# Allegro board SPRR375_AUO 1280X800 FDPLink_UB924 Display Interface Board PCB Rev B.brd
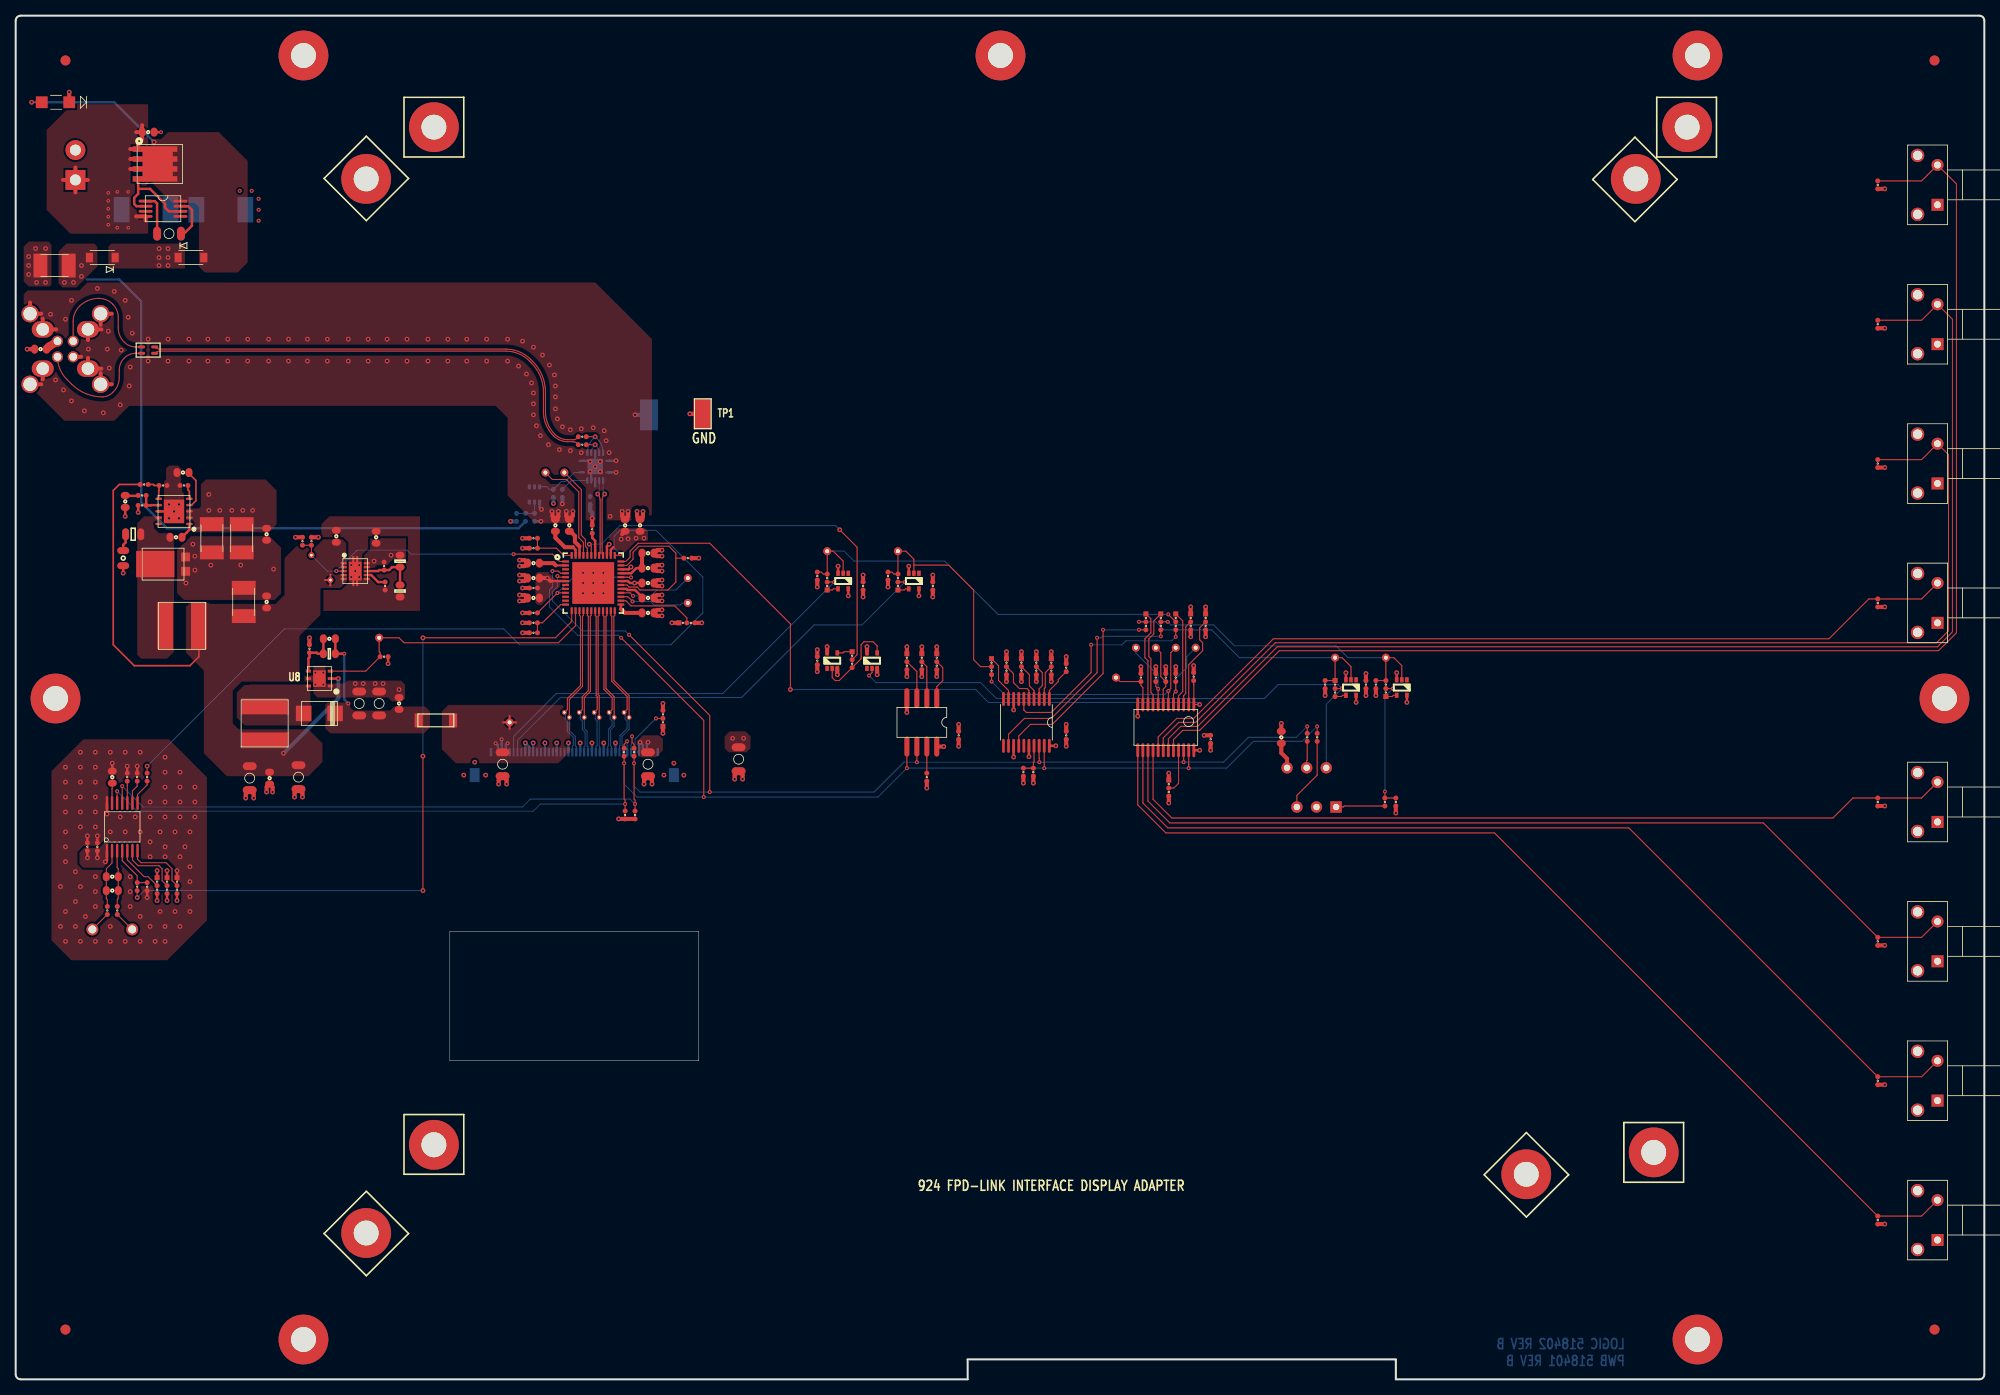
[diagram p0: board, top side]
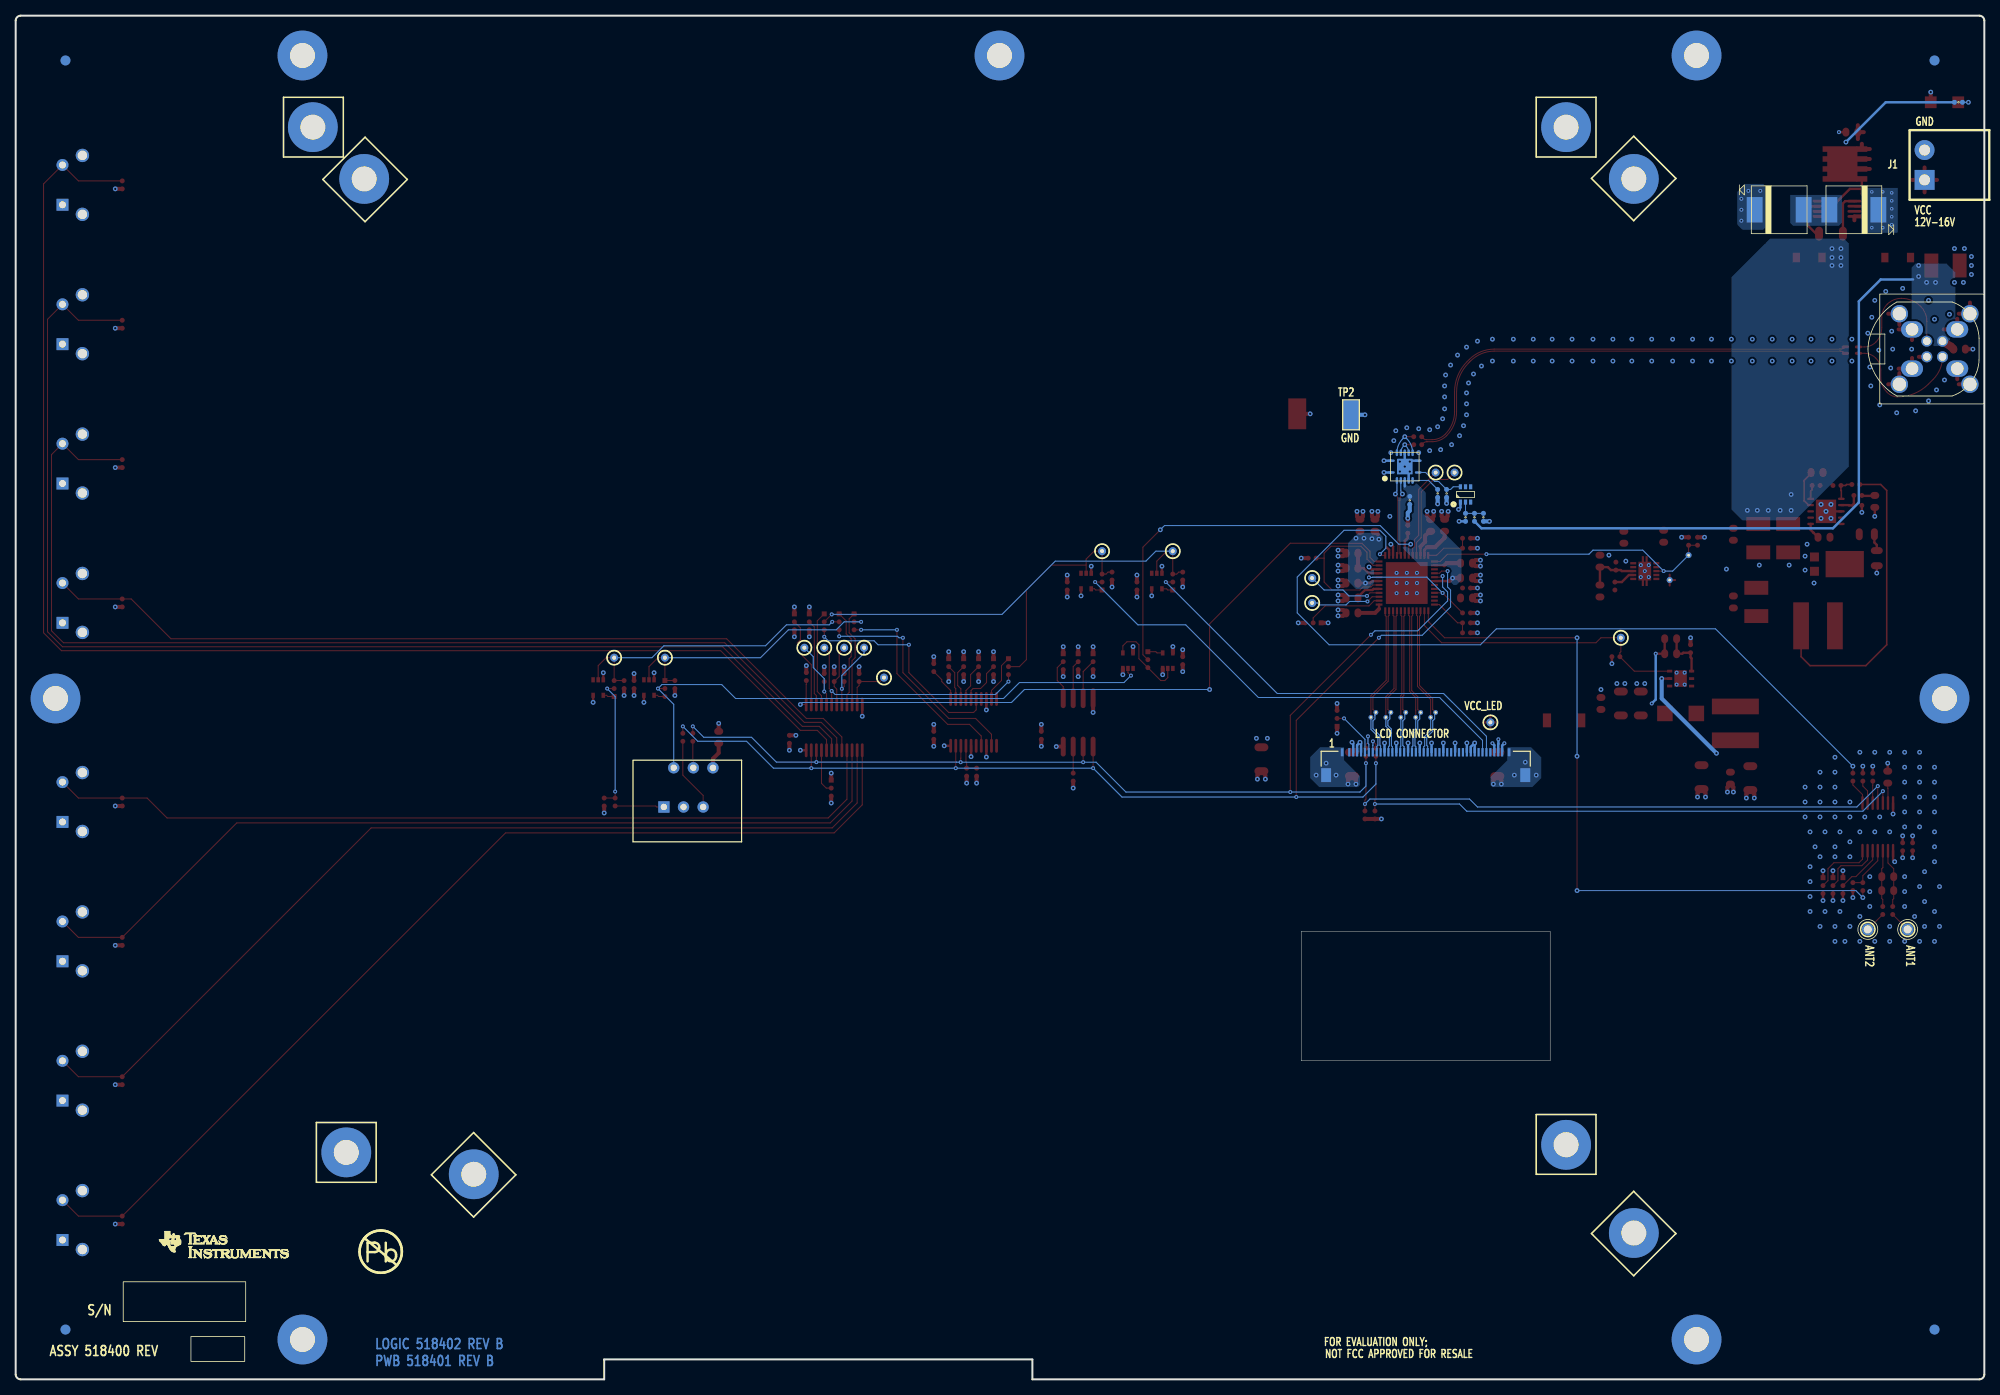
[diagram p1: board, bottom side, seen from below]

Outline 251.08 x 173.99 mm; copper layers: TOP, L2_GND, L3_PWR, BOTTOM. Coordinates in mm from the lower left corner of the outline.
Outline path: circle c53.34,29.97 r1.52 ; circle c208.91,28.96 r1.52 ; 0,173.35 arc(0.19,173.8) 0.64,173.99 250.44,173.99 arc(250.89,173.8) 251.08,173.35 251.08,0.64 arc(250.89,0.19) 250.44,0 176.02,0 176.02,2.54 121.41,2.54 121.41,0 0.64,0 arc(0.19,0.19) 0,0.64 0,173.35 ; 55.37,57.15 55.37,40.64 87.12,40.64 87.12,57.15 55.37,57.15

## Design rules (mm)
net group DP1: nets N48074547 N48074849
net group RIN+: nets N48057923 RIN+
net group RIN-: nets N48057914 RIN-
net group RXN: nets RXINOCLK+ RXINOCLK- RXNO0+ RXNO0- RXNO1+ RXNO1- RXNO2+ RXNO2- RXNO3+ RXNO3-

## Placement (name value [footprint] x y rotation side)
C1  2.7nF  [C603-35X45]  21.34 115.7 0 top
C2  39nF  [C603-35X45]  13.97 112.01 270 top
C3  30pF  [C402-25]  16.13 111.51 0 top
C4  4.7uF  [C603-35X45]  68.83 108.97 90 top
C5  4.7uF  [C603-35X45]  70.61 108.97 270 top
C6  4.7uF  [C603-35X45]  77.72 108.97 270 top
C7  0.1uF  [C402-25]  73.53 108.46 270 top
C8  0.1uF  [C402-25]  72.26 119.25 0 top
C9  0.1uF  [C402-25]  72.26 120.27 0 top
C10  0.22uF  [C603-35X45]  32 107.82 270 top
C11  2.2uF  [C603-35X45]  40.89 107.57 90 top
C12  0.1uF  [C603-35X45]  20.45 107.44 180 top
C13  10uF  [C603-35X45]  45.97 107.44 90 top
C14  4.7uF  [C1210-70X102]  25.02 107.31 270 top
C15  4.7uF  [C1210-70X102]  28.83 107.31 270 top
C16  4.7uF  [C603-35X45]  80.64 105.41 180 top
C17  NP  [C805-35X60]  13.72 104.78 270 top
C18  4.7uF  [C603-35X45]  66.04 104.14 180 top
C19  5.6pF  [C402-25]  46.99 103.76 270 top
C20  4.7uF  [C603-35X45]  80.64 103.5 180 top
C21  4.7uF  [C603-35X45]  66.04 102.23 180 top
C22  4.7uF  [C603-35X45]  80.64 101.6 180 top
C23  0.001uF  [C402-25]  47.12 101.22 270 top
C24  0.1uF  [C402-25]  108.08 101.22 90 top
C25  0.1uF  [C402-25]  116.97 101.22 90 top
C26  0.01uF  [C402-25]  66.04 100.97 0 top
C27  4.7uF  [C603-35X45]  80.64 99.69 0 top
C28  47uF  [C1210-70X102]  29.08 99.19 90 top
C29  0.22uF  [C603-35X45]  32 99.19 90 top
C30  4.7uF  [C603-35X45]  80.64 97.79 0 top
C31  330pF  [C603-35X45]  40.01 94.49 180 top
C32  0.01uF  [C402-25]  102.23 91.69 90 top
C33  0.1uF  [C402-25]  172.21 88.65 90 top
C34  10uF  [C1206-40X70]  43.81 86.23 90 top
C35  NO-POP  [C1206-40X70]  46.35 86.23 90 top
C36  0.1uF  [C603-35X45]  48.9 86.23 270 top
C37  0.1uF  [C402-25]  120.27 82.17 270 top
C38  0.1uF  [C402-25]  133.99 82.17 90 top
C39  10uF  [C603-35X45]  161.42 81.92 90 top
C40  0.1uF  [C402-25]  152.4 81.66 90 top
C41  10uF  [C1206-40X70]  92.2 79.12 90 top
C42  10uF  [C1206-40X70]  62.1 78.49 90 top
C43  10uF  [C1206-40X70]  80.64 78.49 270 top
C44  0.1uF  [C402-25]  129.79 77.47 270 top
C45  1uF  [C603-35X45]  12.32 76.83 90 top
C46  10uF  [C1206-40X70]  36.07 76.83 90 top
C47  10uF  [C1206-40X70]  29.84 76.71 270 top
C48  0.1uF  [C603-35X45]  32.38 76.71 90 top
C49  0.01uF  [C402-25]  9.14 67.94 90 top
C50  1uF  [C402-25]  10.41 67.94 90 top
C51  NP  [C603-35X45]  12.32 64.14 0 top
C52  0.01uF  [C402-25]  16.76 62.87 90 top
C53  NP  [C603-35X45]  12.32 62.36 0 top
C54  0.1uF  [C603-35X45]  3.17 131.44 180 top
C55  4.7uF  [C1210-70X102]  4.95 142.11 0 top
C56  1uF  [C402-25]  36.58 106.93 270 top
C57  2.2uF  [C1206-40X70]  19.56 146.18 0 top
C58  0.22uF  [C603-35X45]  16.89 159.13 0 top
C59  0.01uF  [C402-25]  63.88 109.98 90 bottom
C60  0.01uF  [C402-25]  73.28 112.14 270 bottom
D1  MBRX140-TP  [SOD123-36X48]  11.05 143.13 180 top
D2  PDS760  [DIODE-POWERDI5]  18.8 104.01 180 top
D3  MBRA340T3  [SMA2-78SQ]  38.73 84.96 180 top
D4  SMCJ30A-13-F  [SMC-80X128]  16.64 149.22 0 bottom
D5  MBRX140-TP  [SOD123-36X48]  22.35 143.13 0 top
D6  SMCJ14A-13-F  [SMC-80X128]  26.16 149.22 180 bottom
DS1  LED_GRN  [LED1206-59X59]  5.08 162.94 180 top
FL1  DLW21SN900HQ2  [EMI-36X15-DLW21-RDPADS]  16.89 131.32 0 top
J1  Phoenix - 1803277  [CON2R-150]  7.62 153.03 90 bottom
J2  HEADER 40  [CON40-HD1S040H]  71.25 80.01 180 bottom
J3  MOLEX 39-53-2064  [FPC6_1P25_TH_RA]  168.4 73.03 180 bottom
L1  BLM18AG221SN1D  [L603-35X45]  79.63 108.97 270 top
L2  BLM18AG221SN1D  [L603-35X45]  66.04 99.69 180 top
L3  22uH  [IND2-79X236-6MM]  21.21 96.14 0 top
L4  BLM41PG750SN1L  [FB1806-41X70]  53.59 84.07 0 top
L5  4.7uH  [IND2-79X236-6MM]  31.75 83.69 90 top
MH1  NP  [MHP125-250]  36.7 168.91 0 top
MH2  NP  [MHP125-250]  125.6 168.91 0 top
MH3  NP  [MHP125-250]  44.7 153.16 0 top
MH4  NP  [MHP125-250]  206.63 153.16 0 top
MH5  NP  [MHP125-250]  5.08 86.87 0 top
MH6  NP  [MHP125-250]  246 86.87 0 top
MH7  NP  [MHP125-250]  192.66 26.16 0 top
MH8  NP  [MHP125-250]  44.7 18.67 0 top
MH9  NP  [MHP125-250]  36.7 5.08 0 top
MH10  NP  [MHP125-250]  214.5 5.08 0 top
NOREF  -  []  158.68 68.78 90 top
NOREF#2  -  []  245.87 0 90 top
NOREF#3  -  [unnamed#2]  6.35 6.35 0 top
NOREF#4  -  []  168.4 73.03 0 top
NOREF#5  -  [unnamed#2]  244.73 168.28 0 top
NOREF#6  -  []  -252.73 -240.28 0 top
NOREF#7  -  []  158.68 68.78 0 top
NOREF#8  -  [unnamed#2]  6.35 168.28 0 top
NOREF#9  -  []  55.37 40.64 90 top
NOREF#10  -  []  167.15 78.02 0 top
NOREF#11  -  []  55.37 40.64 0 top
NOREF#12  -  []  253.49 0 90 top
NOREF#13  -  []  -252.73 -240.28 0 top
NOREF#14  -  [unnamed#2]  214.5 168.91 0 top
NOREF#15  -  [unnamed#2]  244.73 6.35 0 top
NOREF#16  -  []  0 173.35 0 top
NOREF#17  -  [unnamed#2]  6.35 168.28 180 bottom
NOREF#18  -  [unnamed#2]  208.91 28.96 180 bottom
NOREF#19  -  []  233.68 15.24 180 bottom
NOREF#20  -  [unnamed#2]  6.35 6.35 180 bottom
NOREF#21  -  [unnamed#2]  53.34 159.77 180 bottom
NOREF#22  -  [unnamed#2]  53.34 29.92 180 bottom
NOREF#23  -  [unnamed#2]  244.73 6.35 180 bottom
NOREF#24  -  [unnamed#2]  213.18 159.77 180 bottom
NOREF#25  -  [unnamed#2]  244.73 168.28 180 bottom
NOREF#26  -  []  207.9 12.83 180 bottom
P2  D4S10E-40MA5-C/D4S20G-400A5-C  [CON_MB261-D4S10E_COMBO]  5.33 132.46 270 bottom
Q1  BSS138PS  [SOT363-16X45]  66.17 112.9 180 bottom
Q3  SQJ422EP  [PWR-Q5A-SLPS319]  15.62 155.07 270 top
R1  60.4K  [R402-25]  16.38 114.17 0 top
R2  11.5K  [R402-25]  18.8 114.05 0 top
R3  133K  [R402-25]  21.46 114.05 180 top
R4  5.9K  [R402-25]  16.13 112.78 180 top
R5  NP  [R805-35X60]  14.99 107.82 180 top
R6  40.2K  [R402-25]  66.04 107.31 180 top
R7  133K  [R402-25]  37.72 106.93 90 top
R8  NP  [R402-25]  66.04 106.05 0 top
R9  10K  [R402-25]  85.72 104.78 180 top
R10  15.8K  [R603-35X45]  49.02 104.39 270 top
R11  10K  [R402-25]  102.23 102.49 90 top
R12  10K  [R402-25]  111.25 102.49 90 top
R13  4.99K  [R603-35X45]  49.02 100.58 270 top
R14  2K  [R402-25]  66.04 97.79 0 top
R15  40.2K  [R402-25]  66.04 96.52 180 top
R16  NP  [R402-25]  66.04 95.25 0 top
R17  10K  [R402-25]  37.47 93.22 270 top
R18  69.8K  [R603-35X45]  40.01 92.58 0 top
R19  10K  [R402-25]  46.99 92.2 0 top
R20  2K  [R402-25]  133.99 90.81 90 top
R21  10K  [R402-25]  150.24 89.66 270 top
R22  10K  [R402-25]  143.51 89.53 270 top
R23  10K  [R402-25]  145.41 89.53 270 top
R24  10K  [R402-25]  146.69 89.53 270 top
R25  10K  [R402-25]  147.96 89.53 270 top
R26  10K  [R402-25]  167 88.65 90 top
R27  10K  [R402-25]  173.48 88.65 90 top
R28  0  [R402-25]  164.72 81.92 270 top
R29  0  [R402-25]  165.99 81.92 270 top
R30  NP  [R402-25]  77.6 80.01 90 top
R31  NP  [R402-25]  78.87 80.01 270 top
R32  10K  [R402-25]  128.52 77.47 90 top
R33  0  [R402-25]  14.22 76.83 270 top
R34  0  [R402-25]  15.49 76.83 270 top
R35  0  [R402-25]  16.76 76.83 270 top
R36  2K  [R402-25]  116.2 76.83 270 top
R37  100  [R402-25]  174.62 73.66 270 top
R38  NP  [R402-25]  176.02 73.66 270 top
R39  5.9K  [R402-25]  77.72 72.01 90 top
R40  5.9K  [R402-25]  78.99 72.01 90 top
R41  0  [R402-25]  15.49 62.87 270 top
R42  0  [R402-25]  11.68 59.82 90 top
R43  0  [R402-25]  12.95 59.82 90 top
R44  1K  [R402-25]  3.3 162.94 0 bottom
R45  10K  [R402-25]  69.72 113.03 90 bottom
R46  10K  [R402-25]  68.58 113.03 270 bottom
R47  11.5K  [R402-25]  65.02 109.98 90 bottom
R48  2K  [R402-25]  66.17 109.98 90 bottom
R49  10K  [R402-25]  237.49 152.4 90 top
R50  10K  [R402-25]  237.49 134.62 90 top
R51  10K  [R402-25]  237.49 116.84 90 top
R52  10K  [R402-25]  237.49 99.06 90 top
R53  10K  [R402-25]  237.49 73.66 90 top
R54  10K  [R402-25]  237.49 38.1 90 top
R55  10K  [R402-25]  237.49 55.88 90 top
R56  10K  [R402-25]  237.49 20.32 90 top
RJ1  100.A  [JMP402-25]  103.5 101.22 90 top
RJ2  100.A  [JMP402-25]  112.52 101.22 90 top
RJ3  0  [JMP402-25]  144.15 97.16 270 top
RJ4  0  [JMP402-25]  146.05 97.16 270 top
RJ5  0  [JMP402-25]  147.96 97.16 270 top
RJ6  10K.A  [JMP402-25]  149.86 97.16 270 top
RJ7  10K.A  [JMP402-25]  151.76 97.16 270 top
RJ8  0  [JMP402-25]  85.09 96.52 0 top
RJ9  100.A  [JMP402-25]  106.68 92.33 270 top
RJ10  10K.A  [JMP402-25]  113.67 92.08 270 top
RJ11  10K.A  [JMP402-25]  115.57 92.08 270 top
RJ12  10K.A  [JMP402-25]  117.47 92.08 270 top
RJ13  0  [JMP402-25]  124.46 91.44 270 top
RJ14  0  [JMP402-25]  126.36 91.44 270 top
RJ15  0  [JMP402-25]  128.27 91.44 270 top
RJ16  0  [JMP402-25]  130.18 91.44 270 top
RJ17  0  [JMP402-25]  132.08 91.44 270 top
RJ18  100.A  [JMP402-25]  168.28 88.65 270 top
RJ19  100.A  [JMP402-25]  174.75 87.63 90 top
RJ20  NP  [JMP402-25]  82.55 83.82 90 top
RJ21  10K.A  [JMP402-25]  147.07 75.95 270 top
RJ22  0  [JMP402-25]  18.03 63.5 270 top
RJ23  0  [JMP402-25]  19.3 63.5 270 top
RJ24  0  [JMP402-25]  20.57 63.5 270 top
SW1  np-ksl0v411lft  [SW2-PUSH-KSL0V]  245.11 152.4 90 top
SW2  np-ksl0v411lft  [SW2-PUSH-KSL0V]  245.11 134.62 90 top
SW3  np-ksl0v411lft  [SW2-PUSH-KSL0V]  245.11 116.84 90 top
SW4  np-ksl0v411lft  [SW2-PUSH-KSL0V]  245.11 99.06 90 top
SW5  np-ksl0v411lft  [SW2-PUSH-KSL0V]  245.11 73.66 90 top
SW6  np-ksl0v411lft  [SW2-PUSH-KSL0V]  245.11 38.1 90 top
SW7  np-ksl0v411lft  [SW2-PUSH-KSL0V]  245.11 55.88 90 top
SW8  np-ksl0v411lft  [SW2-PUSH-KSL0V]  245.11 20.32 90 top
TP1  TPSLP  [TP1-70X135]  87.63 123.19 0 top
TP2  TPSLP  [TP1-70X135]  80.77 123.06 180 bottom
TP3  NP  [TP1-4020]  69.98 115.7 180 bottom
TP4  NP  [TP1-4020]  67.56 115.7 180 bottom
TP5  NP  [TP1-4020]  112.52 105.66 180 bottom
TP6  NP  [TP1-4020]  103.5 105.66 180 bottom
TP7  RD30  [TP-30RD13]  37.72 105.16 0 bottom
TP8  NP  [TP1-4020]  85.72 102.23 180 bottom
TP9  RD30  [TP-30RD13]  40.13 101.98 0 bottom
TP10  NP  [TP1-4020]  85.72 99.06 180 bottom
TP11  NP  [TP1-4020]  46.35 94.61 270 bottom
TP12  NP  [TP1-4020]  150.5 93.34 0 bottom
TP13  NP  [TP1-4020]  147.96 93.34 0 bottom
TP14  NP  [TP1-4020]  145.41 93.34 0 bottom
TP15  NP  [TP1-4020]  142.88 93.34 0 bottom
TP16  NP  [TP1-4020]  174.75 92.08 180 bottom
TP17  NP  [TP1-4020]  168.28 92.08 180 bottom
TP18  NP  [TP1-4020]  140.34 89.53 0 bottom
TP19  NP  [TP-24RD12]  77.6 85.09 90 bottom
TP20  NP  [TP-24RD12]  75.69 85.09 90 bottom
TP21  NP  [TP-24RD12]  73.79 85.09 90 bottom
TP22  NP  [TP-24RD12]  71.88 85.09 90 bottom
TP23  NP  [TP-24RD12]  69.98 85.09 90 bottom
TP24  NP  [TP-24RD12]  78.23 84.45 90 bottom
TP25  NP  [TP-24RD12]  76.33 84.45 90 bottom
TP26  NP  [TP-24RD12]  74.42 84.45 90 bottom
TP27  NP  [TP-24RD12]  72.52 84.45 90 bottom
TP28  NP  [TP-24RD12]  70.61 84.45 90 bottom
TP29  NP  [TP1-4020]  62.99 83.82 180 bottom
TP30  TestPoint1  [TP1-6040]  14.86 57.4 180 bottom
TP31  TestPoint1  [TP1-6040]  9.78 57.4 180 bottom
U1  TPS54361QDPRTQ1  [DPR10]  20.19 110.74 90 top
U2  TPS74701  [DRC10-11X33]  43.31 103.12 270 top
U3  SN74LVC1G04DCK  [DCK-5]  105.54 101.85 180 top
U4  SN74LVC1G04DCK  [DCK-5]  114.55 101.85 180 top
U5  DS90UB924-Q1  [RHS48-11X34]  73.66 101.6 270 top
U6  SN74LVC1G04DCK  [DCK-5]  104.14 91.69 0 top
U7  SN74LVC1G04DCK  [DCK-5]  109.22 91.69 0 top
U8  LM2735XSD/NOPB  [NGG6]  38.73 89.41 90 top
U9  NP-SN74LVC1G04DCK  [DCK-5]  170.31 88.27 180 top
U10  SN74LVC1G04DCK  [DCK-5]  176.78 88.27 180 top
U11  24WC256  [SO8-25X75-295]  115.57 83.82 180 top
U12  TLC59108IPW  [PW20-14X70]  128.91 83.82 180 top
U13  PCF8575  [PW24-14X70]  146.69 83.19 180 top
U14  RF430CL330H  [PW14-12X70]  13.59 70.48 0 top
U16  LM74610  [DGK8-14X70]  18.8 149.35 270 top
U17  HD3SS3411-Q1  [RWA14]  73.91 116.46 180 bottom

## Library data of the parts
C1 C2 C12 C17 C57 = CAP NP_0: Tolerance: X; User Part Number: X
C3 C50 C56 = CAP NP_0: Tolerance: TOLERANCE; User Part Number: USERPART#
C4-C6 C10 C16 C18 C20-C22 C27 C29 C30 C39 C43 C58 = CAP: Tolerance: X; User Part Number: X
C7 C24-C26 C32 C33 C38 C40 C44 C49 C52 C59 C60 = CAP: Tolerance: TOLERANCE; User Part Number: USERPART#
C8 C9 = CAP: Tolerance: TOLERANCE; User Part Number: USERPART#; signal model: CAP_C402-25_0.1UF
C11 C13 C31 C34-C36 C47 C48 C54 = CAP NP: Tolerance: X; User Part Number: X
C14 C15 C55 = CAP_AM_0805_10uf_x7r_10v_10_X: User Part Number: X; Tolerance: X
C19 = Cap 100nF Cermc 16V 10% 603_0: Tolerance: TOLERANCE; User Part Number: USERPART#
C23 = CAP NP: Tolerance: TOLERANCE; User Part Number: USERPART#
C28 = CAP P: User Part Number: X; Tolerance: X
C37 = CAP .1 uF 10% 0603: Tolerance: TOLERANCE; User Part Number: USERPART#
C41 C42 C46 = C_10uF/6.3V_X5R_0603: Tolerance: X; User Part Number: X
C45 C51 C53 = CAP_AM_0603_1.0uf_x7r_16v_10_X: Tolerance: X; User Part Number: X
D1 D5 = DIODE_0: User Part Number: USERPART#; Tolerance: TOLERANCE
D2 = PDS760
D3 = Diode_5ARect: User Part Number: X; Tolerance: X
D4 D6 = Diode_SMCJ15CA
DS1 = LED_RED_0: Tolerance: X; User Part Number: X
FL1 = DLW21SN900HQ2: User Part Number: PART#; Tolerance: TOL
J1 = HEADER 2
J2 = HEADER 40_1: Tolerance: TOL; User Part Number: PART#
J3 = CON6
L1 L2 L4 = FERRITE CHIP_0: Tolerance: X; User Part Number: X
L3 = INDUCTOR IRON: Tolerance: TOLERANCE; User Part Number: USERPART#
L5 = INDUCTOR: Tolerance: TOLERANCE; User Part Number: USERPART#
MH1-MH10 TP30 TP31 = TestPoint1_0
P2 = D4S20G_D4S10E
Q1 = BSS138PS: User Part Number: X; Tolerance: X
Q3 = MOSFET_CSD16406Q3_0: User Part Number: X; Tolerance: X
R1-R4 R44 = R_2: Tolerance: TOLERANCE; User Part Number: USERPART#
R5 = R_2: Tolerance: X; User Part Number: X
R6-R9 R15-R17 R45-R47 = R: Tolerance: TOLERANCE; User Part Number: USERPART#
R10 R13 = R_3: User Part Number: X; Tolerance: X
R11 R12 R14 R19-R43 R48-R56 = RESISTOR: Tolerance: TOLERANCE; User Part Number: USERPART#
R18 = R: User Part Number: X; Tolerance: X
RJ1-RJ7 RJ9-RJ24 = RJUMP3: Tolerance: TOLERANCE; User Part Number: USERPART#
RJ8 = RJUMP3A: Tolerance: TOLERANCE; User Part Number: USERPART#
SW1-SW8 = ksl0v411lft: Tolerance: X; User Part Number: X
TP1 TP2 = SMT-TP
TP3-TP6 TP8 TP10-TP29 = TESTPOINT
TP7 TP9 = TESTPOINT: Tolerance: TOLERANCE; User Part Number: USERPART#
U1 = TPS54361QDPRRQ1: Tolerance: X; User Part Number: X
U2 = U-TPS78601_AJUST - 1_0.5A LDO: Tolerance: X; User Part Number: X
U3 U4 U6 U7 U9 U10 = SN74LVC1GU04_0: Tolerance: TOL; User Part Number: PART#
U5 = DS90UB924Q
U8 = LM2735
U11 = 24WC256: User Part Number: X; Tolerance: X
U12 = TLC59108IPW_TSSOP20: Tolerance: X; User Part Number: X
U13 = PCF8575_1: Tolerance: X; User Part Number: X
U14 = RF430CL330H: User Part Number: USERPART#; Tolerance: TOLERANCE
U16 = LM74610: User Part Number: X; Tolerance: X
U17 = HD3SS3411-Q1: User Part Number: X; Tolerance: X

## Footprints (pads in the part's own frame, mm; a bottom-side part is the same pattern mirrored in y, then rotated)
C402-25
  round 0.635 smd: 1(-0.508,0) 2(0.508,0)
C603-35X45
  oval 0.889x1.143 smd: 1(-0.762,0) 2(0.762,0)
C805-35X60
  oval 0.889x1.524 smd: 1(-0.965,0) 2(0.965,0)
C1206-40X70
  oval 1.016x1.778 smd: 1(-1.524,0) 2(1.524,0)
C1210-70X102
  rect 1.778x3.048 smd: 1(-1.803,0) 2(1.803,0)
CON2R-150
  rect 2.54x2.54 hole 1.397: 1(0,0)
  round 2.54 hole 1.397: 2(3.81,0)
CON40-HD1S040H
  rect 0.279x1.067 smd: 1(-9.748,0) 2(-9.248,0) 3(-8.748,0) 4(-8.248,0) 5(-7.748,0) 6(-7.248,0) 7(-6.748,0) 8(-6.248,0) 9(-5.749,0) 10(-5.249,0) 11(-4.749,0) 12(-4.249,0) 13(-3.749,0) 14(-3.249,0) 15(-2.749,0) 16(-2.249,0) 17(-1.75,0) 18(-1.25,0) 19(-0.75,0) 20(-0.25,0) 21(0.25,0) 22(0.75,0) 23(1.25,0) 24(1.75,0) 25(2.249,0) 26(2.749,0) 27(3.249,0) 28(3.749,0) 29(4.249,0) 30(4.749,0) 31(5.249,0) 32(5.749,0) 33(6.248,0) 34(6.748,0) 35(7.248,0) 36(7.748,0) 37(8.248,0) 38(8.748,0) 39(9.248,0) 40(9.748,0)
  rect 1.27x1.778 smd: 41(-12.7,-2.921) 42(12.7,-2.921)
  rect 0.356x1.016 smd: 43(-10.643,0) 44(10.643,0)
CON_MB261-D4S10E_COMBO
  round 1.397 hole 0.991: 1(2,-2) 2(2,0) 3(0,0) 4(0,-2)
  round 2.21 hole 1.702: SH1(-3.5,3.5) SH2(-3.5,-5.5) SH3(5.5,-5.5) SH4(5.5,3.5)
  oval 2.083x2.794 hole 1.6: SH1A(3.503,-3.884) SH2A(3.503,1.882) SH3A(-1.501,1.882) SH4A(-1.501,-3.884)
DCK-5
  rect 0.46x0.66 smd: 1(-0.65,-0.991) 2(0,-0.991) 3(0.65,-0.991) 4(0.65,0.991) 5(-0.65,0.991)
DGK8-14X70
  oval 0.356x1.778 smd: 1(-0.975,-2.225) 2(-0.325,-2.225) 3(0.325,-2.225) 4(0.975,-2.225) 5(0.975,2.223) 6(0.325,2.223) 7(-0.325,2.223) 8(-0.975,2.223)
DIODE-POWERDI5
  rect 1.143x1.143 smd: ANODE1(-2.87,0.914) ANODE2(-2.87,-0.914)
  rect 4.877x3.353 smd: CATHODE(0.991,0)
DPR10
  oval 0.305x0.864 smd: 1(-1.6,-1.956) 2(-0.8,-1.956) 3(0,-1.956) 4(0.8,-1.956) 5(1.6,-1.956) 6(1.6,1.956) 7(0.8,1.956) 8(0,1.956) 9(-0.8,1.956) 10(-1.6,1.956)
  rect 2.997x2.591 smd: 11(0,0)
DRC10-11X33
  rect 0.305x0.762 smd: 1(-1.001,-1.473) 2(-0.5,-1.473) 3(0,-1.473) 4(0.5,-1.473) 5(1.001,-1.473) 6(1.001,1.473) 7(0.5,1.473) 8(0,1.473) 9(-0.5,1.473) 10(-1.001,1.473)
  custom 0.406x0.406 smd: 11(0,0)
EMI-36X15-DLW21-RDPADS
  oval 0.914x0.381 smd: 1(-0.838,0.406) 2(0.838,0.406) 3(0.838,-0.406) 4(-0.838,-0.406)
FB1806-41X70
  rect 1.041x1.778 smd: 1(-2.184,0) 2(2.184,0)
FPC6_1P25_TH_RA
  rect 1.448x1.448 hole 0.813: 1(0,0)
  round 1.448 hole 0.813: 2(1.25,5) 3(2.5,0) 4(3.75,5) 5(5,0) 6(6.25,5)
IND2-79X236-6MM
  rect 2.007x5.994 smd: 1(-2.159,0) 2(2.159,0)
JMP402-25
  rect 0.635x0.635 smd: 1(-0.508,0)
  round 0.635 smd: 2(0.508,0) 3(1.524,0)
L603-35X45
  oval 0.889x1.143 smd: 1(-0.762,0) 2(0.762,0)
LED1206-59X59
  rect 1.499x1.499 smd: 1(-1.753,0) 2(1.753,0)
MHP125-250
  round 6.35 hole 3.175: 1(0,0)
NGG6
  rect 0.356x0.66 smd: 1(-0.95,-1.397) 2(0,-1.397) 3(0.95,-1.397) 4(0.95,1.397) 5(0,1.397) 6(-0.95,1.397)
  rect 2.108x1.6 smd: 7(0,0)
PW14-12X70
  oval 0.305x1.778 smd: 1(-1.951,-3.048) 2(-1.3,-3.048) 3(-0.65,-3.048) 4(0,-3.048) 5(0.65,-3.048) 6(1.3,-3.048) 7(1.951,-3.048) 8(1.951,3.048) 9(1.3,3.048) 10(0.65,3.048) 11(0,3.048) 12(-0.65,3.048) 13(-1.3,3.048) 14(-1.951,3.048)
PW20-14X70
  oval 0.356x1.778 smd: 1(-2.926,-2.987) 2(-2.276,-2.987) 3(-1.626,-2.987) 4(-0.975,-2.987) 5(-0.325,-2.987) 6(0.325,-2.987) 7(0.975,-2.987) 8(1.626,-2.987) 9(2.276,-2.987) 10(2.926,-2.987) 11(2.926,2.987) 12(2.276,2.987) 13(1.626,2.987) 14(0.975,2.987) 15(0.325,2.987) 16(-0.325,2.987) 17(-0.975,2.987) 18(-1.626,2.987) 19(-2.276,2.987) 20(-2.926,2.987)
PW24-14X70
  oval 0.356x1.778 smd: 1(-3.576,-2.921) 2(-2.926,-2.921) 3(-2.276,-2.921) 4(-1.626,-2.921) 5(-0.975,-2.921) 6(-0.325,-2.921) 7(0.325,-2.921) 8(0.975,-2.921) 9(1.626,-2.921) 10(2.276,-2.921) 11(2.926,-2.921) 12(3.576,-2.921) 13(3.576,2.921) 14(2.926,2.921) 15(2.276,2.921) 16(1.626,2.921) 17(0.975,2.921) 18(0.325,2.921) 19(-0.325,2.921) 20(-0.975,2.921) 21(-1.626,2.921) 22(-2.276,2.921) 23(-2.926,2.921) 24(-3.576,2.921)
PWR-Q5A-SLPS319
  rect 0.711x1.397 smd: 1(-1.905,0) 2(-0.635,0) 3(0.635,0) 4(1.905,0)
  custom 1.111x1.111 smd: 5(0,2.781)
R402-25
  round 0.635 smd: 1(-0.508,0) 2(0.508,0)
R603-35X45
  oval 0.889x1.143 smd: 1(-0.762,0) 2(0.762,0)
R805-35X60
  oval 0.889x1.524 smd: 1(-0.965,0) 2(0.965,0)
RHS48-11X34
  rect 0.279x0.864 smd: 1(-2.748,-3.531) 2(-2.25,-3.531) 3(-1.75,-3.531) 4(-1.25,-3.531) 5(-0.749,-3.531) 6(-0.249,-3.531) 7(0.249,-3.531) 8(0.749,-3.531) 9(1.25,-3.531) 10(1.75,-3.531) 11(2.25,-3.531) 12(2.748,-3.531) 25(2.748,3.531) 26(2.25,3.531) 27(1.75,3.531) 28(1.25,3.531) 29(0.749,3.531) 30(0.249,3.531) 31(-0.249,3.531) 32(-0.749,3.531) 33(-1.25,3.531) 34(-1.75,3.531) 35(-2.25,3.531) 36(-2.748,3.531)
  rect 0.864x0.279 smd: 13(3.531,-2.748) 14(3.531,-2.25) 15(3.531,-1.75) 16(3.531,-1.25) 17(3.531,-0.749) 18(3.531,-0.249) 19(3.531,0.249) 20(3.531,0.749) 21(3.531,1.25) 22(3.531,1.75) 23(3.531,2.25) 24(3.531,2.748) 37(-3.531,2.748) 38(-3.531,2.25) 39(-3.531,1.75) 40(-3.531,1.25) 41(-3.531,0.749) 42(-3.531,0.249) 43(-3.531,-0.249) 44(-3.531,-0.749) 45(-3.531,-1.25) 46(-3.531,-1.75) 47(-3.531,-2.25) 48(-3.531,-2.748)
  rect 5.334x5.334 smd: 49(0,0)
RWA14
  oval 0.864x0.305 smd: 1(-1.714,-0.749) 7(1.714,-0.749) 8(1.714,0.749) 14(-1.714,0.749)
  oval 0.305x0.864 smd: 2(-1.003,-1.765) 3(-0.503,-1.765) 4(-0.003,-1.765) 5(0.498,-1.765) 6(0.998,-1.765) 9(0.998,1.765) 10(0.498,1.765) 11(-0.003,1.765) 12(-0.503,1.765) 13(-1.003,1.765)
  rect 1.981x1.981 smd: 15(0,0)
SMA2-78SQ
  rect 1.981x1.981 smd: 1(-2.007,0) 2(2.007,0)
SMC-80X128
  rect 2.032x3.251 smd: 1(-3.124,0) 2(3.124,0)
SO8-25X75-295
  oval 0.635x2.54 smd: 1(-1.905,-3.086) 2(-0.635,-3.086) 3(0.635,-3.086) 4(1.905,-3.086) 5(1.905,3.086) 6(0.635,3.086) 7(-0.635,3.086) 8(-1.905,3.086)
SOD123-36X48
  rect 0.914x1.219 smd: 1(-1.638,0) 2(1.638,0)
SOT363-16X45
  rect 0.406x0.635 smd: 1(-0.65,-0.978) 2(0,-0.978) 3(0.65,-0.978) 4(0.65,0.978) 5(0,0.978) 6(-0.65,0.978)
SW2-PUSH-KSL0V
  rect 1.524x1.524 hole 0.889: 1(-2.54,0)
  round 1.524 hole 0.889: 2(2.54,0)
  round 1.702 hole 1.194: 3(-3.759,2.54) 4(3.759,2.54)
TP1-70X135
  rect 2.286x3.937 smd: 1(0,0)
TP1-4020
  round 1.016 hole 0.508: 1(0,0)
TP1-6040
  round 1.524 hole 1.016: 1(0,0)
TP-24RD12
  round 0.61 hole 0.305: 1(0,0)
TP-30RD13
  round 0.762 hole 0.33: 1(0,0)
unnamed#2
  round 1.27 smd: 1(0,0)

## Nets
GND: C1.1 C2.2 C3.1 C4.2 C5.1 C6.1 C7.1 C10.2 C11.2 C13.2 C14.2 C15.2 C16.1 C17.2 C18.2 C20.1 C21.2 C22.1 C23.2 C24.2 C25.2 C26.1 C27.2 C28.2(CATHODE) C29.2 C30.2 C32.1 C33.2 C34.2 C35.2 C36.1 C37.1 C38.2 C39.2 C40.2 C41.1 C42.1 C43.2 C44.2 C45.2 C46.1 C47.2 C48.1 C49.2 C50.2 C52.1 C54.2 C55.1 C56.1 C58.2 C59.1 C60.2 D2.ANODE1 D2.ANODE2 D6.1(CATHODE) DS1.1(CATHODE) J1.2 J2.10 J2.13 J2.16 J2.19 J2.22 J2.25 J2.28 J2.31 J2.32 J2.33 J2.41(MT1) J2.42(MT2) J2.43(MT3) J2.44(MT4) J3.3 P2.1 P2.SH1 P2.SH1A P2.SH2 P2.SH2A P2.SH3 P2.SH3A P2.SH4 P2.SH4A Q1.1(S2) R2.2 R3.2 R6.2 R13.2 R14.1 R15.2 R17.1 R19.2 R20.2 R33.1 R34.1 R36.2 R38.2 R45.1 R48.1 RJ6.3 RJ7.3 RJ8.1 RJ10.3 RJ11.3 RJ12.3 RJ14.1 RJ15.1 RJ16.1 RJ17.1 RJ20.3 RJ21.3 RJ22.1 RJ23.1 RJ24.1 SW1.1 SW2.1 SW3.1 SW4.1 SW5.1 SW6.1 SW7.1 SW8.1 TP1.1 TP2.1 U1.8(GND) U1.11(PAD) U2.6(GND) U2.11(PP1) U3.3(GND) U4.3(GND) U5.34(RES0) U5.39(RES1) U5.49(DAP(PWRPAD)) U6.3(GND) U7.3(GND) U8.1(PGND) U8.5(AGND) U8.7(PAD) U9.3(GND) U10.3(GND) U11.4(VSS) U12.8(GND1) U12.13(GND2) U12.16(GND3) U13.12(GND) U14.14(VSS) U17.1(OENN) U17.5(GND#5) U17.8(GND#8) U17.11(GND#11) U17.14(GND#14) U17.15(PAD)
VCC_LED: C42.2 J2.38 J2.39 J2.40 L4.2 TP29.1(TP)
VCC_LED_EN: R19.1 TP11.1(TP) U5.14(GPIO0/SWC) U8.3(EN)
VDD33_AB: C6.2 C22.2 L1.2 U5.31(VDD33_B) U5.38(VDD33_A)
VDDIO: C21.1 C26.2 C60.1 L2.1 U5.6(VDDIO) U17.4(VCC)
A0: RJ17.2 U12.2(A0)
A1: RJ16.2 U12.3(A1)
A2: RJ15.2 U12.4(A2)
A3: RJ14.2 U12.5(A3)
ANT1: C51.1 C53.1 R42.2 U14.2(ANT1)
ANT2: C51.2 C53.2 R43.2 U14.3(ANT2)
CAPI2S: C18.1 U5.2(CAPI2S)
CAPL12: C16.2 C20.2 U5.33(CAPL12)
CAPLV12: C27.1 U5.29(CAPLV12)
CAPLV25: C30.1 U5.25(CAPLV25)
CAPP12: C4.1 U5.47(CAPP12)
CAPR12: C5.2 U5.46(CAPR12)
CHG: RJ9.2 U5.43(INTB_IN)
DC_5V: C11.1 C28.1(ANODE) C29.1 C46.2 C47.1 C48.2 L3.2 L5.1 R1.1 TP9.1(TP) U2.1(IN1) U2.2(IN2) U2.4(BIAS) U2.5(EN) U8.2(VIN)
EEPROM_A0: RJ12.2 U11.1(A0)
EEPROM_A1: RJ11.2 U11.2(A1)
EEPROM_NC: RJ10.2 U11.3(NC)
EVM_3V3: C13.1 C19.1 C24.1 C25.1 C32.2 C33.1 C37.2 C38.1 C39.1 C40.1 C41.2 C43.1 C49.1 C50.1 J2.2 J2.3 J2.4 J3.6 L1.1 L2.2 R7.2 R8.1 R9.1 R10.1 R11.1 R12.1 R16.1 R21.1 R22.1 R23.1 R24.1 R25.1 R26.1 R27.1 R32.1 R39.1 R40.1 R46.2 R49.1 R50.1 R51.1 R52.1 R53.1 R54.1 R55.1 R56.1 RJ6.1 RJ7.1 RJ8.3 RJ10.1 RJ11.1 RJ12.1 RJ14.3 RJ15.3 RJ16.3 RJ17.3 RJ20.1 RJ21.1 RJ22.3 RJ23.3 RJ24.3 U2.9(VOUT1) U2.10(VOUT2) U3.5(VCC) U4.5(VCC) U6.5(VCC) U7.5(VCC) U9.5(VCC) U10.5(VCC) U11.8(VCC) U12.20(VCC) U13.24(VDD) U14.1(VCC)
LCD_I2C_SCL: R28.1 R31.2 R40.2 U5.5(SCL) U11.6(SCL) U12.18(SCL) U13.22(SCL) U14.11(MISO/SCI)
LCD_I2C_SDA: R29.1 R30.1 R39.2 U5.4(SDA) U11.5(SDA) U12.19(SDA) U13.23(SDA) U14.12(MOSI/SDA)
LED_EN: J2.36 RJ1.2
LED_PWM: J2.35 RJ2.2
PB_INTR: R21.2 U5.36(I2S_DD/GPIO3) U13.1(I\N\T\)
PB_SW1: R49.2 SW1.2 U13.20(P17)
PB_SW2: R50.2 SW2.2 U13.19(P16)
PB_SW3: R51.2 SW3.2 U13.18(P15)
PB_SW4: R52.2 SW4.2 U13.17(P14)
PB_SW5: R53.2 SW5.2 U13.16(P13)
PB_SW6: R55.2 SW7.2 U13.15(P12)
PB_SW7: R54.2 SW6.2 U13.14(P11)
PB_SW8: R56.2 SW8.2 U13.13(P10)
PCF8575_OUT0: RJ5.1 U13.4(P0)
PCF8575_OUT1: R25.2 TP12.1(TP) U13.5(P1)
PCF8575_OUT2: RJ13.3 TP13.1(TP) U13.6(P2)
PCF8575_OUT3: R24.2 TP14.1(TP) U13.7(P3)
PCF8575_OUT4: R23.2 TP15.1(TP) U13.8(P4)
PCF8575_OUT5: RJ4.1 U13.9(P5)
PCF8575_OUT6: RJ3.1 U13.10(P6)
PCF8575_OUT7: R22.2 TP18.1(TP) U13.11(P7)
PG_VPOC: C56.2 R7.1 TP7.1(TP) U2.3(PG) U5.1(PDB)
RF_INTR: R35.1 U5.37(I2S_DC/GPIO2)
RF_RSTN: R41.2 U5.13(GPIO1/SDOUT)
RIN+: C9.2 U17.9(CN) U17.13(BP)
RIN-: C8.2 U17.10(CP) U17.12(BN)
RST_1: C44.1 R32.2 U12.17(R\E\S\E\T\)
RXINOCLK+: J2.18 TP22.1(TP) U5.17(TXCLKOUT+)
RXINOCLK-: J2.17 TP27.1(TP) U5.18(TXCLCKOUT-)
RXNO0+: J2.9 TP19.1(TP) U5.23(TXOUT0+)
RXNO0-: J2.8 TP24.1(TP) U5.24(TXOUT0-)
RXNO1+: J2.12 TP20.1(TP) U5.21(TXOUT1+)
RXNO1-: J2.11 TP25.1(TP) U5.22(TXOUT1-)
RXNO2+: J2.15 TP21.1(TP) U5.19(TXOUT2+)
RXNO2-: J2.14 TP26.1(TP) U5.20(TXOUT2-)
RXNO3+: J2.21 TP23.1(TP) U5.15(TXOUT3+)
RXNO3-: J2.20 TP28.1(TP) U5.16(TXOUT3-)
TLC5910_OUT0: RJ5.3 U12.6(O\U\T\0\)
TLC5910_OUT2: RJ13.1 U12.9(O\U\T\2\)
TLC5910_OUT5: RJ4.3 U12.12(O\U\T\5\)
TLC5910_OUT6: RJ3.3 U12.14(O\U\T\6\)
TOUCH_IRQ: J3.2 RJ18.2 U7.2(I)
TOUCH_RSTN: R37.1 R38.1 RJ19.2
TPA+: FL1.1 P2.4
TPA-: FL1.4 P2.2
TPANT1: R43.1 TP30.1
TPANT2: R42.1 TP31.1
VEXT_DISPLAY: D5.2(ANODE) Q3.5(D1) R44.2 U16.8(CATHODE)
VPOC_DISPLAY: C54.1 C55.2 D1.2(ANODE) P2.3 R47.1
N47950634: RJ21.2 U13.21(A0)
N47950640: RJ7.2 U13.2(A1)
N47950646: RJ6.2 U13.3(A2)
N47950787: R26.2 RJ3.2 RJ18.1 TP17.1(TP) U9.2(I)
N47950851: R11.2 RJ1.3 RJ5.2 TP6.1(TP) U3.2(I)
N47950958: RJ1.1 U3.4(O)
N47950978: RJ19.1 U10.4(O)
N47951040: R27.2 RJ4.2 RJ19.3 TP16.1(TP) U10.2(I)
N47952362: R12.2 RJ2.3 RJ13.2 TP5.1(TP) U4.2(I)
N47961891: J2.7 R30.2
N47961914: J2.6 R31.1
N47962004: J2.5 RJ20.2
N47962200: J3.1 R37.2
N47962259: J3.5 R29.2
N47962261: J3.4 R28.2
N47962324: RJ9.3 U6.2(I) U7.4(O)
N47962345: RJ9.1 U6.4(O)
N47969957: RJ2.1 U4.4(O)
N47970052: RJ18.3 U9.4(O)
N47970092: R20.1 U12.1(REXT)
N47983015: R6.1 R8.2 U5.48(MODE_SEL)
N47983017: R15.1 R16.2 U5.12(IDX)
N47983700: R9.2 U5.30(OEN) U5.35(OSS_SEL)
N47983709: R14.2 U5.9(BISTEN) U5.32(LFMODE)
N47985043: RJ8.2 U5.26(MAPSEL)
N47986219: C7.2 U5.42(CMF)
N47992682: R36.1 U11.7(WP)
N48000930: D3.2(ANODE) L5.2 U8.6(SW)
N48000983: C31.1 C34.1 C35.1 C36.2 D3.1(CATHODE) L4.1 R18.2
N48001081: C31.2 R17.2 R18.1 U8.4(FP)
N48004915: C12.1 U1.1(BOOT)
N48004919: C12.2 D2.CATHODE L3.1 R5.1 U1.9(SW)
N48004949: C17.1 R5.2
N48005041: C10.1 C14.1 C15.1 D1.1(CATHODE) D5.1(CATHODE) U1.2(VIN) U1.3(EN)
N48005170: C1.2 U1.4(SS_TR)
N48005174: C3.2 R4.1 U1.7(COMP)
N48005180: C19.2 R10.2 R13.1 U2.8(FB)
N48005190: C23.1 U2.7(SS)
N48005198: R3.1 U1.5(RT_CLK)
N48005202: R1.2 R2.1 U1.6(FB)
N48008865: TP8.1(TP) U5.28(PASS)
N48008866: TP10.1(TP) U5.27(LOCK)
N48038498: C45.1 U14.13(VCORE)
N48038546: C52.2 R41.1 U14.4(RST)
N48038552: RJ22.2 U14.5(E0)
N48038556: R33.2 U14.10(SCK)
N48038560: RJ23.2 U14.6(E1)
N48038564: R34.2 U14.9(SCMS/CSN)
N48038573: RJ24.2 U14.7(E2)
N48038577: R35.2 U14.8(INTO)
N48057914: C8.1 FL1.3
N48057923: C9.1 FL1.2
N48071870: Q3.4(G) U16.2(GT PULL DWN) U16.6(GATE DRV)
N48071884: C57.1 U16.1(VCAPL)
N48071888: C57.2 U16.7(VCAPH)
N48071920: C58.1 D4.1(CATHODE) J1.1 Q3.1(S1) Q3.2(S2) Q3.3(S3) U16.4(ANODE)
N48071988: D4.2(ANODE) D6.2(ANODE)
N48071992: DS1.2(ANODE) R44.1
N48074547: U5.40(RIN+) U17.2(AP)
N48074849: U5.41(RIN-) U17.3(AN)
N48077474: Q1.6(D2) R46.1 U17.7(SEL)
N48078230: C59.2 Q1.2(G2) R47.2 R48.2
N48128501: R45.2 U17.6(RSVD6)
N480053081: C2.1 R4.2
N4797957014: TP3.1(TP) U5.44(CMLOUTP)
N4797957015: TP4.1(TP) U5.45(CMLOUTN)

Pads without a net: J2 1 23 24 26 27 29 30 34 37; MH1 1; MH2 1; MH3 1; MH4 1; MH5 1; MH6 1; MH7 1; MH8 1; MH9 1; MH10 1; NOREF#3 1; NOREF#5 1; NOREF#8 1; NOREF#14 1; NOREF#15 1; NOREF#17 1; NOREF#18 1; NOREF#20 1; NOREF#21 1; NOREF#22 1; NOREF#23 1; NOREF#24 1; NOREF#25 1; Q1 3 4 5; SW1 3 4; SW2 3 4; SW3 3 4; SW4 3 4; SW5 3 4; SW6 3 4; SW7 3 4; SW8 3 4; U1 10; U3 1; U4 1; U5 3 7 8 10 11; U6 1; U7 1; U9 1; U10 1; U12 7 10 11 15; U16 3 5

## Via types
v1: diameter 0.61, hole 0.305, TOP to BOTTOM, 418 vias
v2: diameter 0.457, hole 0.203, TOP to BOTTOM, 9 vias
v3: diameter 0.508, hole 0.254, TOP to BOTTOM, 78 vias
v4: diameter 0.635, hole 0.305, TOP to BOTTOM, 5 vias

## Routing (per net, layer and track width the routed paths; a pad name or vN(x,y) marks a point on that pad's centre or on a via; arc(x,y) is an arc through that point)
GND: length 237
  TOP w0.305: R19.2 v1(47.5,91.31) ; RJ24.1 v1(20.57,64.9) ; C49.2 v1(9.14,69.34) ; C58.2 v3(18.54,159.13) ; U1.8 v4(20.19,110.74) ; RJ22.1 v1(18.03,64.9) ; U12.16 v1(129.23,79.45) ; RJ23.1 v1(19.3,64.9) ; U12.13 v1(127.28,79.4) ; C45.2 v1(12.32,78.61) ; U5.34 78.18,103.35 v1(78.47,103.65) ; C52.1 v1(16.76,61.47) ; U5.39 75.41,106.27 v1(75.69,106.55) ; 15.62,111.51 v1(15.62,110.62) ; U13.12 v1(143.11,84.6) ; 15.49,77.34 v1(15.49,78.23) ; U14.14 v1(11.64,72.14) ; 14.22,77.34 v1(14.22,78.23) ; U4.3 v1(113.9,103.74) ; C50.2 v1(10.41,69.34) ; U3.3 v1(104.89,103.74) ; U10.3 v1(176.13,90.15) ; U9.3 v1(169.66,90.15) ; C17.2 v1(13.72,102.87) ; U12.8 v1(127.28,85.41) ; C2.2 v1(13.97,110.11)
  TOP w0.508: RJ6.3 v1(149.86,94.74) ; RJ8.1 v1(83.69,96.52) ; v1(82.42,100.08) 81.79,100.08 C27.2 81.79,99.31 v1(82.42,99.31) ; RJ21.3 v1(147.07,73.53) ; v1(32,74.93) 32,75.56 C48.1 32.77,75.56 v1(32.77,74.93) ; R6.2 v1(64.64,107.31) ; v1(70.23,110.74) 70.23,110.11 C5.1 71.07,110.19 v1(71.07,110.74) ; v1(82.42,97.41) 81.79,97.41 C30.2 81.79,98.17 v1(82.42,98.17) ; v1(82.42,105.03) 81.79,105.03 C16.1 81.79,105.79 v1(82.42,105.79) ; v1(30.35,74.17) 30.35,74.68 C47.2 29.34,74.68 v1(29.34,74.17) ; v1(82.42,101.22) 81.79,101.22 C22.1 81.79,101.98 v1(82.42,101.98) ; P2.1 8.35,130.46 ; 3.26,135.96 P2.SH1 1.83,137.38 ; U7.3 v1(109.87,89.9) ; RJ11.3 v1(115.57,89.66) ; 10.93,128.96 P2.SH1A 9.22,130.32 ; 9.22,132.6 P2.SH4A 10.93,133.96 ; RJ17.1 v1(132.08,92.84) ; C33.2 v1(172.21,90.04) ; DS1.1 v1(6.83,164.24) ; C37.1 v1(120.27,83.57) ; U6.3 v1(104.79,89.9) ; 108.08,101.73 v1(108.08,102.62) ; 116.97,101.73 v1(116.97,102.62) ; RJ12.3 v1(117.47,89.66) ; v1(80.14,75.94) 80.14,76.45 C43.2 81.15,76.46 v1(81.16,75.95) ; C40.2 v1(151.57,82.17) ; v1(64.26,101.85) 64.9,101.85 C21.2 64.9,102.62 v1(64.26,102.62) ; 12.26,126.96 P2.SH3 10.83,128.38 ; RJ15.1 v1(128.27,92.84) ; R20.2 v1(133.99,92.2) ; 12.26,135.96 P2.SH2 10.83,134.54 ; R15.2 v1(64.64,96.52) ; v1(82.42,103.12) 81.79,103.12 C20.1 81.79,103.89 v1(82.42,103.89) ; P2.SH4 3.26,126.96 ; R36.2 v1(116.2,75.44) ; C38.2 v1(133.99,83.57) ; v1(69.22,110.74) 69.22,110.11 C4.2 68.45,110.11 68.45,110.67 v1(68.38,110.74) ; RJ20.3 v1(82.55,86.23) ; TP1.1 v1(85.98,123.19) ; C56.1 v1(35.69,107.44) ; v1(91.7,76.58) 91.7,77.09 C41.1 92.71,77.09 v1(92.71,76.58) ; v1(62.61,75.95) 62.61,76.46 C42.1 61.6,76.45 v1(61.6,75.94) ; C39.2 v1(161.42,83.69) ; v1(35.56,74.29) 35.56,74.8 C46.1 36.58,74.8 v1(36.58,74.3) ; 5.17,133.96 P2.SH3A 3.45,135.32 ; v1(64.26,103.76) 64.9,103.76 C18.2 64.9,104.52 v1(64.26,104.52) ; RJ7.3 v1(151.76,94.74) ; RJ14.1 v1(126.36,92.84) ; C54.2 v1(1.46,131.44) ; R17.1 v1(37.47,94.61) ; RJ16.1 v1(130.18,92.84) ; C7.1 v1(73.53,109.86) ; RJ10.3 v1(113.67,89.66) ; R38.2 v1(176.02,72.26) ; v1(77.34,110.74) 77.34,110.11 C6.1 78.11,110.11 v1(78.11,110.74) ; C26.1 v1(64.64,100.97) ; 3.45,127.6 P2.SH2A ; C32.1 v1(102.23,90.3) ; R14.1 v1(64.64,97.79) ; U11.4 v1(113.67,85.09) ; C44.2 v1(129.79,76.07)
  L2_GND w0.254: 245.11,52.26 SW7.1 ; SW7.1 246.19,53.34 ; SW7.1 244.03,53.34 ; SW7.1 245.11,54.42 ; 9.41,135.96 P2.SH2 ; P2.SH2 10.83,137.38 ; P2.SH2 12.26,135.96 ; P2.SH2 10.83,134.54 ; P2.SH4A 9.22,135.3 ; P2.SH4A 7.88,133.96 ; P2.SH4A 10.55,133.96 ; P2.SH4A 9.22,132.63 ; SW1.1 246.19,149.86 ; SW1.1 245.11,148.78 ; SW1.1 245.11,150.94 ; SW1.1 244.03,149.86 ; 3.45,132.63 P2.SH3A ; P2.SH3A 4.79,133.96 ; P2.SH3A 3.45,135.3 ; P2.SH3A 2.12,133.96 ; 1.83,134.54 P2.SH1 ; P2.SH1 1.83,137.38 ; P2.SH1 3.26,135.96 ; SW6.1 246.19,35.56 ; SW6.1 245.11,36.64 ; SW6.1 244.03,35.56 ; SW6.1 245.11,34.48 ; 244.03,114.3 SW3.1 ; SW3.1 245.11,115.38 ; SW3.1 245.11,113.22 ; SW3.1 246.19,114.3 ; P2.SH1A 9.22,130.29 ; P2.SH1A 9.22,127.62 ; P2.SH1A 10.55,128.96 ; P2.SH1A 7.88,128.96 ; 6.03,156.84 J1.2 ; J1.2 7.62,158.43 ; J1.2 7.62,155.26 ; J1.2 9.21,156.84 ; 244.03,17.78 SW8.1 ; SW8.1 246.19,17.78 ; SW8.1 245.11,16.7 ; SW8.1 245.11,18.86 ; P2.SH4 1.83,128.38 ; P2.SH4 1.83,125.54 ; P2.SH4 3.26,126.96 ; P2.SH2A 3.45,130.29 ; P2.SH2A 3.45,127.62 ; P2.SH2A 4.79,128.96 ; P2.SH2A 2.12,128.96 ; SW2.1 245.11,133.16 ; SW2.1 244.03,132.08 ; SW2.1 245.11,131 ; SW2.1 246.19,132.08 ; SW5.1 245.11,72.2 ; SW5.1 246.19,71.12 ; SW5.1 244.03,71.12 ; SW5.1 245.11,70.04 ; 244.03,96.52 SW4.1 ; SW4.1 246.19,96.52 ; SW4.1 245.11,95.44 ; SW4.1 245.11,97.6 ; J3.3 165.9,74.07 ; J3.3 166.94,73.03 ; J3.3 165.9,71.98 ; J3.3 164.86,73.03 ; 8.35,130.46 P2.1 7.33,129.44 ; 10.83,125.54 P2.SH3 ; P2.SH3 10.83,128.38 ; P2.SH3 9.41,126.96
  BOTTOM w0.305: U17.1 v1(76.57,115.71) ; U17.8 73.16,117.21 v1(73.28,117.09) v1(73.91,116.46) ; J2.13 v1(75,81.19) ; J2.22 v1(70.5,81.19) ; J2.10 v1(76.5,81.19) ; U17.5 73.42,115.69 v1(73.28,115.82) v1(73.91,116.46) ; U17.11 73.92,116.46 v1(73.91,116.46) ; J2.31 v1(66,81.19) ; J2.19 v1(72,81.19) ; v1(67.06,111) 66.82,111.24 Q1.1 ; J2.33 v1(65,81.19) 65.5,80.69 J2.32 ; J2.25 v1(69,81.19) ; J2.16 v1(73.5,81.19) ; R48.1 v1(66.99,109.47) ; U17.14 v1(76.57,117.21) ; J2.28 v1(67.5,81.19)
  BOTTOM w0.508: v1(73.53,109.86) 73.53,110.57 73.28,110.82 73.28,111.63 ; R45.1 v1(69.72,111.7) ; C59.1 v1(63.12,109.47) ; TP2.1 v1(78.99,123.06)
  vias: v1(1.65,143.26) v1(1.65,142.11) v1(1.65,140.97) v1(1.91,135.89) v1(2.54,144.27) v1(2.67,139.95) v1(3.81,144.27) v1(3.81,139.95) v1(4.45,135.89) v1(5.08,127.51) v1(5.71,62.87) v1(5.71,57.78) v1(6.1,126.24) v1(6.35,135.25) v1(6.35,78.11) v1(6.35,76.2) v1(6.35,74.3) v1(6.35,72.39) v1(6.35,69.85) v1(6.35,67.94) v1(6.35,66.04) v1(6.35,59.69) v1(6.35,55.88) v1(7.11,137.67) v1(7.11,124.84) v1(7.62,64.77) v1(7.62,60.96) v1(7.62,57.78) v1(8.26,80.01) v1(8.26,78.11) v1(8.26,76.2) v1(8.26,74.3) v1(8.26,72.39) v1(8.26,70.48) v1(8.26,62.87) v1(8.26,55.88) v1(8.76,123.57) v1(8.89,59.05) v1(9.27,131.44) v1(10.16,80.01) v1(10.16,78.11) v1(10.16,76.2) v1(10.16,74.3) v1(10.16,72.39) v1(10.16,70.48) v1(10.16,64.14) v1(10.16,62.23) v1(10.16,60.33) v1(10.16,55.88) v1(10.41,139.19) v1(11.18,123.32) v1(11.68,131.44) v1(11.81,133.73) v1(11.94,129.03) v1(12.06,80.01) v1(12.06,69.85) v1(12.06,57.78) v1(12.06,55.88) v1(12.57,138.81) v1(13.34,124.33) v1(13.34,71.75) v1(13.46,131.32) v1(13.97,137.67) v1(13.97,80.01) v1(13.97,69.85) v1(13.97,55.88) v1(14.35,135.51) v1(14.48,126.75) v1(14.61,129.16) v1(14.61,64.14) v1(14.61,62.23) v1(14.61,60.33) v1(14.86,133.48) v1(15.24,71.75) v1(15.88,80.01) v1(15.88,69.85) v1(15.88,59.05) v1(15.88,55.88) v1(16.89,132.72) v1(16.89,129.92) v1(17.14,73.66) v1(17.14,71.75) v1(17.14,68.58) v1(17.14,66.67) v1(17.14,57.78) v1(17.78,55.88) v1(18.41,69.85) v1(18.41,59.69) v1(19.05,79.38) v1(19.05,77.47) v1(19.05,75.56) v1(19.05,73.66) v1(19.05,71.75) v1(19.05,67.94) v1(19.05,66.67) v1(19.05,57.78) v1(19.05,55.88) v1(19.43,132.72) v1(19.43,129.92) v1(20.32,69.85) v1(20.32,59.69) v1(20.95,77.47) v1(20.95,75.56) v1(20.95,73.66) v1(20.95,71.75) v1(20.95,66.67) v1(20.95,57.78) v1(21.59,67.94) v1(21.72,101.6) v1(22.1,132.72) v1(22.1,129.92) v1(22.23,69.85) v1(22.23,65.41) v1(22.23,63.5) v1(22.23,61.59) v1(22.23,59.69) v1(22.61,106.55) v1(22.86,105.03) v1(22.86,103.25) v1(22.86,75.56) v1(22.86,73.66) v1(22.86,71.75) v1(24.51,132.72) v1(24.51,129.92) v1(24.89,103.89) v1(27.05,132.72) v1(27.05,129.92) v1(28.7,103.89) v1(29.59,132.72) v1(29.59,129.92) v1(32.26,132.72) v1(32.26,129.92) v1(32.89,103.38) v1(34.8,132.72) v1(34.8,129.92) v1(37.21,132.72) v1(37.21,129.92) v1(39.75,132.72) v1(39.75,129.92) v1(42.42,132.72) v1(42.42,129.92) v1(43.31,88.77) v1(44.32,88.77) v1(44.96,132.72) v1(44.96,129.92) v1(45.85,88.77) v1(46.86,88.77) v1(47.37,132.72) v1(47.37,129.92) v1(48.9,88.01) v1(49.91,132.72) v1(49.91,129.92) v1(52.58,132.72) v1(52.58,129.92) v1(55.12,132.72) v1(55.12,129.92) v1(57.15,77.09) v1(57.53,132.72) v1(57.53,129.92) v1(58.55,78.74) v1(59.94,77.09) v1(60.07,132.72) v1(60.07,129.92) v1(62.74,132.72) v1(62.74,129.92) v1(64.14,129.29) v1(64.64,132.46) v1(65.15,128.27) v1(65.79,127.13) v1(66.04,131.7) v1(66.04,125.86) v1(66.04,124.46) v1(66.04,123.06) v1(66.42,121.67) v1(66.93,120.4) v1(67.18,130.68) v1(67.94,119.25) v1(68.07,129.41) v1(68.71,128.14) v1(68.83,126.75) v1(68.83,125.35) v1(68.83,123.83) v1(69.09,122.56) v1(69.34,118.62) v1(69.72,121.54) v1(70.74,121.16) v1(70.74,118.49) v1(72.14,121.28) v1(72.14,118.24) v1(73.66,121.41) v1(74.55,117.09) v1(74.55,115.82) v1(75.06,121.03) v1(75.31,119.76) v1(75.69,118.24) v1(75.82,110.11) v1(82.68,77.09) v1(83.95,78.61) v1(85.22,77.09) v3(28.57,151.64) v3(30.1,151.64) v3(30.99,150.62) v3(30.99,149.22) v3(30.99,147.83) v3(38.23,90.17) v3(38.23,88.65) v3(39.24,90.17) v3(39.24,88.65) v3(42.8,103.89) v3(42.8,102.36) v3(43.31,103.12) v3(43.81,103.89) v3(43.81,102.36) v3(72.36,102.9) v3(72.36,101.6) v3(72.36,100.3) v3(73.66,102.9) v3(73.66,101.6) v3(73.66,100.3) v3(74.96,102.9) v3(74.96,101.6) v3(74.96,100.3) v4(19.56,111.63) v4(19.56,109.86) v4(20.83,111.63) v4(20.83,109.86)
VCC_LED: length 7.5
  TOP w0.254: 62.17,83.82 TP29.1 ; TP29.1 62.99,82.99 ; TP29.1 63.82,83.82 ; TP29.1 62.99,84.65
  BOTTOM w0.305: v3(61.21,81.15) 61.5,80.87 J2.40 ; v3(61.98,81.66) 61.98,81.08 62,81.05 J2.39 ; v3(62.74,81.15) 62.5,80.91 J2.38
VCC_LED_EN: length 37.7
  TOP w0.127: U8.3 44.64,90.36 R19.1 46.48,92.71 46.35,92.84 TP11.1 48.9,94.61 49.53,93.98 69.22,93.98 71.41,96.17 U5.14
VDD33_AB: length 4.5
  TOP w0.305: U5.38 75.91,105.84 76.24,106.17 ; U5.31 78.1,101.85 78.35,101.6 v1(78.93,101.6) C22.2
  TOP w0.508: 77.34,107.82 C6.2
  vias: v1(77.22,107.19) v1(78.11,107.25) v1(79.12,107.31) v1(80.14,107.31)
VDDIO: length 4.3
  TOP w0.305: U5.6 68.2,101.85
  TOP w0.508: C21.1 v1(67.82,102.23) 68.2,101.85
  BOTTOM w0.305: 73.92,113.92 U17.4
A0: length 4.5
  TOP w0.127: U12.2 131.18,88.13 131.32,88.27 131.32,90.17 RJ17.2
A1: length 4.6
  TOP w0.127: RJ16.2 130.94,90.17 130.94,88.52 130.53,88.11 U12.3
A2: length 4.8
  TOP w0.127: RJ15.2 129.29,89.92 129.29,88.48 129.88,87.89 U12.4
A3: length 5.9
  TOP w0.127: RJ14.2 127.25,90.04 127.25,88.9 128.02,88.14 128.98,88.14 129.23,87.89 U12.5
ANT1: length 7.5
  TOP w0.127: R42.2 11.68,61.2 11.56,61.33 C53.1 C51.1 11.56,65.15 12.29,65.88 U14.2
ANT2: length 7.2
  TOP w0.127: U14.3 12.94,65.29 13.08,65.15 13.08,61.34 12.95,61.22 R43.2
CAPI2S: length 3.4
  TOP w0.254: U5.2 68.87,103.85
  TOP w0.508: 68.87,103.85 68.58,104.14 C18.1
CAPL12: length 4.9
  TOP w0.305: C20.2 79.16,103.5 78.5,102.85 U5.33
  TOP w0.508: C20.2 C16.2
CAPLV12: length 3.2
  TOP w0.305: C27.1 79.88,99.82 78.99,100.71 78.04,100.71 77.9,100.85 U5.29
CAPLV25: length 3.5
  TOP w0.305: U5.25 77.19,98.3
  TOP w0.508: 77.19,98.3 77.7,97.79 C30.1
CAPP12: length 4.7
  TOP w0.305: 71.08,106.17 71.41,105.84 U5.47
  TOP w0.508: C4.1 68.83,107.38 70.04,106.17 71.08,106.17
CAPR12: length 3.7
  TOP w0.305: 71.91,106.27 U5.46
  TOP w0.508: 71.91,106.27 71.32,106.86 71.32,107.62 70.74,108.2 C5.2
CHG: length 52.4
  TOP w0.127: v1(105.09,108.39) 107.31,106.17 107.31,92.46 RJ9.2 ; v1(73.16,106.55) 73.41,106.3 U5.43
  BOTTOM w0.127: v1(105.09,108.39) 104.55,108.93 103.53,108.93 77.06,108.93 74.68,106.55 v1(73.16,106.55)
DC_5V: length 55.4
  TOP w0.203: R1.1 13.21,114.17 12.45,113.41 12.45,93.73 15.11,91.06 22.23,91.06 23.37,92.2 L3.2
  TOP w0.254: 39.43,101.98 TP9.1 ; TP9.1 40.13,102.68 ; TP9.1 40.13,101.28
  TOP w0.305: U8.2 v1(41.15,89.41)
  BOTTOM w0.508: v1(34.16,79.88) 41.15,86.87 v1(41.15,89.41)
EEPROM_A0: length 5.3
  TOP w0.127: RJ12.2 118.24,90.81 118.24,89.15 117.47,88.39 U11.1
EEPROM_A1: length 4.9
  TOP w0.127: RJ11.2 116.2,90.93 U11.2
EEPROM_NC: length 5.2
  TOP w0.127: RJ10.2 114.94,90.3 114.94,86.91
EVM_3V3: length 69.3
  TOP w0.305: U12.20 v1(132.65,80.83) ; U10.5 v1(177.43,86.38) ; C50.1 v1(10.41,66.55) ; U13.24 v1(151,80.26) ; U4.5 v1(115.2,99.96) ; U14.1 11.64,66.25 v1(11.43,66.04) ; RJ22.3 v1(18.03,61.09) ; U9.5 v1(170.96,86.38) ; RJ24.3 v1(20.57,61.09) ; C49.1 v1(9.14,66.55) ; RJ23.3 v1(19.3,61.09) ; U3.5 v1(106.19,99.96)
  TOP w0.508: R32.1 v1(128.52,76.07) ; R27.1 v1(173.48,87.25) ; RJ8.3 v1(87.5,96.52) ; R40.1 R39.1 v1(76.9,71.5) ; 111.25,101.98 v1(111.25,101.09) ; R26.1 v1(167,87.25) ; RJ17.3 v1(132.08,89.03) ; 147.96,90.04 v1(147.96,90.93) ; v1(64.26,99.31) 64.9,99.31 L2.2 64.9,100.08 v1(64.26,100.08) ; R21.1 v1(150.24,91.06) ; 143.51,90.04 v1(143.51,90.93) ; J3.6 162.15,79.18 161.42,79.92 C39.1 ; R8.1 v1(64.64,106.05) ; v1(79.25,110.74) 79.25,110.11 L1.1 80.01,110.11 v1(80.01,110.74) ; C40.1 v1(152.4,80.26) ; RJ7.1 v1(151.76,98.55) ; R9.1 v1(87.12,104.78) ; U11.8 v1(118.36,80.73) ; RJ12.1 v1(117.47,93.47) ; C25.1 v1(116.97,99.82) ; 102.23,101.98 v1(102.23,101.09) ; R53.1 v1(238.38,73.15) ; U6.5 v1(103.49,93.49) ; RJ21.1 v1(147.07,77.34) ; RJ6.1 v1(149.86,98.55) ; C32.2 v1(102.23,93.09) ; R54.1 v1(238.38,37.59) ; C37.2 v1(120.27,80.77) ; R55.1 v1(238.38,55.37) ; RJ20.1 v1(82.55,82.42) ; RJ15.3 v1(128.27,89.03) ; C38.1 v1(133.99,80.77) ; R51.1 v1(238.38,116.33) ; R49.1 v1(238.38,151.89) ; R50.1 v1(238.38,134.11) ; R7.2 v1(38.61,107.44) ; C24.1 v1(108.08,99.82) ; R52.1 v1(238.38,98.55) ; R16.1 v1(64.64,95.25) ; RJ16.3 v1(130.18,89.03) ; 145.41,90.04 v1(145.41,90.93) ; RJ11.1 v1(115.57,93.47) ; RJ14.3 v1(126.36,89.03) ; 146.69,90.04 v1(146.69,90.93) ; C33.1 v1(172.21,87.25) ; R56.1 v1(238.38,19.81) ; U7.5 v1(108.57,93.49) ; RJ10.1 v1(113.67,93.47)
  L3_PWR w0.254: J3.6 163.19,78.02 ; J3.6 162.15,79.07 ; J3.6 162.15,76.98 ; J3.6 161.11,78.02
  BOTTOM w0.305: J2.3 79.99,80.91 v1(79.63,81.28) 79.49,81.15 J2.4 ; v1(80.64,81.28) 80.49,81.13 J2.2
  BOTTOM w0.508: R46.2 v1(68.58,111.76)
  vias: v1(45.72,104.39) v1(47.88,105.16) v1(91.44,81.79) v1(92.84,81.79)
LCD_I2C_SCL: length 215.9
  TOP w0.127: v3(164.72,83.31) R28.1 ; v3(130.56,78.74) 130.56,79.24 130.53,79.26 U12.18 ; v3(88.52,74.93) 88.52,84.71 v3(78.23,95) ; 114.94,80.73 v3(114.94,78.74) ; v3(69.09,102.49) 69.09,102.48 69.22,102.35 U5.5 ; R40.2 v3(78.99,73.41) 78.99,73.9 78.87,74.03 v3(78.87,78.61) R31.2 ; U14.11 v3(13.59,75.69) ; U13.22 v3(148.96,78.75)
  BOTTOM w0.127: v3(69.09,102.49) 69.09,101.09 68.45,100.46 68.45,99.31 72.26,95.5 77.72,95.5 v3(78.23,95) ; v3(78.99,73.41) 78.36,74.04 65.66,74.04 64.64,73.03 16.26,73.03 v3(13.59,75.69) ; v3(164.72,83.31) 163.32,81.92 157.23,81.92 154.06,78.75 v3(148.96,78.75) 131.06,78.75 131.05,78.74 v3(130.56,78.74) v3(114.94,78.74) 113.28,78.74 109.47,74.93 v3(88.52,74.93) 79.63,74.93 78.87,75.69 v3(78.87,78.61)
LCD_I2C_SDA: length 221
  TOP w0.127: R39.2 v3(77.72,73.41) 77.72,73.9 77.6,74.03 v3(77.6,78.61) R30.1 ; U14.12 v3(12.94,75.04) ; v3(149.61,77.98) 149.61,78.48 149.61,78.49 U13.23 ; v3(68.45,103.12) 69.22,103.12 69.49,102.85 U5.4 ; R29.1 v3(165.99,83.31) ; v3(87.76,74.3) 87.76,84.07 v3(77.22,94.61) ; U11.5 v3(113.67,77.98) ; U12.19 v3(131.18,77.98)
  BOTTOM w0.127: v3(165.99,83.31) 164.08,81.41 157.86,81.41 154.43,77.98 v3(149.61,77.98) v3(131.18,77.98) v3(113.67,77.98) 109.98,74.3 v3(87.76,74.3) 79.25,74.3 77.6,75.95 v3(77.6,78.61) ; v3(68.45,103.12) 68.45,101.09 68.07,100.71 68.07,98.55 71.69,94.93 76.9,94.93 v3(77.22,94.61) ; v3(77.72,73.41) 66.93,73.41 66.01,72.49 15.49,72.49 v3(12.94,75.04)
LED_EN: length 52
  TOP w0.127: 103.5,101.73 v3(104.39,101.73)
  BOTTOM w0.127: v3(104.39,101.73) 90.17,87.5 68.96,87.5 63.5,82.04 J2.36
LED_PWM: length 60.2
  TOP w0.127: 112.52,101.73 v3(113.41,101.73)
  BOTTOM w0.127: J2.35 64,81.52 69.47,87 92.58,87 101.85,96.27 107.95,96.27 v3(113.41,101.73)
PB_INTR: length 92.5
  TOP w0.127: v1(151,86.11) U13.1 150.26,88.63 150.24,88.65 R21.2 ; v1(98.81,88.01) 98.81,96.39 88.52,106.68 79.38,106.68 78.36,105.66 78.36,104.89 77.81,104.35 U5.36
  BOTTOM w0.127: v1(151,86.11) 150.75,86.36 124.08,86.36 122.43,88.01 v1(98.81,88.01)
PB_SW1: length 176
  TOP w0.127: U13.20 147.66,81.62 148.84,82.8 151,82.8 161.16,92.96 245.24,92.96 247.52,95.25 247.52,152.53 SW1.2 243.08,152.91 R49.2
PB_SW2: length 158.2
  TOP w0.127: U13.19 147.01,81.73 148.59,83.31 150.75,83.31 160.91,93.47 245.11,93.47 247.01,95.38 247.01,135.25 SW2.2 243.08,135.13 R50.2
PB_SW3: length 140.3
  TOP w0.127: U13.18 146.36,81.84 148.34,83.82 150.5,83.82 160.66,93.98 244.98,93.98 246.51,95.5 246.51,117.98 SW3.2 243.08,117.35 R51.2
PB_SW4: length 109.2
  TOP w0.127: U13.17 145.71,81.96 148.08,84.33 150.24,84.33 160.4,94.49 231.27,94.49 236.35,99.57 R52.2 243.08,99.57 SW4.2
PB_SW5: length 109.2
  TOP w0.127: SW5.2 243.08,74.17 R53.2 234.31,74.17 231.78,71.63 147.45,71.63 145.06,74.02 U13.16
PB_SW6: length 115.2
  TOP w0.127: SW7.2 243.08,56.39 R55.2 222.88,70.99 147.19,70.99 144.41,73.78 U13.15
PB_SW7: length 123.4
  TOP w0.127: SW6.2 243.08,38.61 R54.2 205.74,70.36 146.94,70.36 143.76,73.54 U13.14
PB_SW8: length 131.5
  TOP w0.127: SW8.2 243.08,20.83 R56.2 188.59,69.72 146.69,69.72 143.11,73.3 U13.13
PCF8575_OUT0: length 12.1
  TOP w0.127: RJ5.1 148.84,96.77 148.84,87.76 148.31,87.22 U13.4
PCF8575_OUT1: length 9.7
  TOP w0.127: U13.5 147.66,87.46 v3(147.96,87.76) R25.2
  BOTTOM w0.127: v3(147.96,87.76) 147.96,89.41 149.35,90.81 149.35,92.2 TP12.1
PCF8575_OUT2: length 31.9
  TOP w0.127: RJ13.3 v3(124.46,89.03) ; U13.6 v3(147.01,87.83) 147.32,88.14 147.32,92.71 TP13.1
  BOTTOM w0.127: v3(124.46,89.03) 126.11,87.38 146.56,87.38 v3(147.01,87.83)
PCF8575_OUT3: length 7.9
  TOP w0.127: U13.7 146.36,88.07 146.69,88.39 R24.2 146.05,89.66 146.05,92.71 TP14.1
PCF8575_OUT4: length 9.5
  TOP w0.127: R23.2 145.41,88.39 v3(145.71,88.1) U13.8
  BOTTOM w0.127: v3(145.71,88.1) 145.71,89.81 142.88,92.65 TP15.1
PCF8575_OUT5: length 12.4
  TOP w0.127: RJ4.1 145.16,96.77 145.16,95.12 144.53,94.49 144.53,92.2 144.78,91.95 144.78,87.63 145.06,87.35 U13.9
PCF8575_OUT6: length 12.3
  TOP w0.127: U13.10 144.41,91.68 144.02,92.08 144.02,94.49 144.78,95.25 144.78,97.03 RJ3.1
PCF8575_OUT7: length 6.4
  TOP w0.127: U13.11 143.76,88.27 143.51,88.52 R22.2 140.84,89.03 TP18.1
PG_VPOC: length 38.3
  TOP w0.127: C56.2 R7.1 TP7.1 ; U2.3 v3(40.89,103.12) ; U5.1 69.39,104.35 68.45,105.28 v3(63.5,105.28)
  BOTTOM w0.127: v3(63.5,105.28) 50.42,105.28 49.91,105.79 43.56,105.79 v3(40.89,103.12) 39.75,103.12 TP7.1
RF_INTR: length 103.5
  TOP w0.127: v3(77.09,105.28) 76.94,105.13 U5.37 ; v1(16.76,78.23) 16.76,77.34
  BOTTOM w0.127: v3(77.09,105.28) 76.33,106.05 76.33,107.57 77.09,108.33 81.66,108.33 87.63,102.36 87.63,97.79 83.57,93.73 64.26,93.73 62.23,95.76 34.29,95.76 v1(16.76,78.23)
RF_RSTN: length 91.2
  TOP w0.127: v1(51.94,94.61) 68.83,94.61 70.87,96.65 70.87,96.77 70.91,96.82 U5.13 ; v1(51.94,62.36) v1(51.94,79.5) ; R41.2 v1(15.49,61.47)
  BOTTOM w0.127: v1(51.94,94.61) v1(51.94,79.5) ; v1(51.94,62.36) 16.38,62.36 v1(15.49,61.47)
RIN+: length 5.8
  TOP w0.13: C9.2 v1(73.91,120.27)
  BOTTOM w0.13: U17.13 arc(74.73,119.19) 74.18,120 v1(73.91,120.27) 73.66,120.01 arc(73.11,119.19) U17.9
RIN-: length 3.5
  TOP w0.13: C8.2 v1(73.91,119.25)
  BOTTOM w0.13: U17.10 arc(73.51,118.71) 73.79,119.13 v1(73.91,119.25) 74.05,119.12 arc(74.32,118.71) U17.12
RST_1: length 4.2
  TOP w0.127: U12.17 129.88,78.78 129.79,78.69 C44.1 R32.2
RXINOCLK+: length 18.9
  TOP w0.13: TP22.1 72.26,85.47 72.26,87.1 73.03,87.87 73.03,97.35 72.91,97.48 U5.17
  BOTTOM w0.13: TP22.1 72.01,84.96 72.01,84.26 72.26,84.01 72.26,82.93 72.62,82.58 72.62,80.83 72.5,80.71 J2.18
RXINOCLK-: length 18.6
  TOP w0.13: TP27.1 72.52,85.36 72.52,85.36 72.52,87 73.29,87.77 73.29,97.35 73.41,97.48 U5.18
  BOTTOM w0.13: J2.17 73,80.71 72.87,80.83 72.87,82.68 72.52,83.04 TP27.1
RXNO0+: length 19.6
  TOP w0.13: U5.23 75.91,97.47 76.03,97.35 76.03,89.07 77.98,87.12 77.98,85.47 TP19.1
  BOTTOM w0.13: TP19.1 77.72,84.97 77.72,84.71 77.72,84.26 77.98,84.01 77.98,83.04 77.09,82.15 77.09,80.9 77,80.81 J2.9
RXNO0-: length 19.3
  TOP w0.13: U5.24 76.41,97.47 76.29,97.35 76.29,89.18 78.23,87.23 78.23,84.46 TP24.1
  BOTTOM w0.13: J2.8 77.5,80.75 77.34,80.9 77.34,82.04 78.23,82.93 TP24.1
RXNO1+: length 19.1
  TOP w0.13: TP20.1 76.07,85.47 76.07,87 75.03,88.04 75.03,97.35 74.91,97.48 U5.21
  BOTTOM w0.13: J2.12 75.5,80.71 75.62,80.83 75.62,82.97 76.07,83.42 76.07,84.01 75.82,84.26 75.82,84.97 TP20.1
RXNO1-: length 18.8
  TOP w0.13: TP25.1 76.33,87.1 75.29,88.14 75.29,97.35 75.41,97.48 U5.22
  BOTTOM w0.13: J2.11 76,80.71 75.87,80.83 75.87,82.86 76.33,83.31 TP25.1
RXNO2+: length 18.5
  TOP w0.13: U5.19 73.91,97.48 74.03,97.35 74.03,87.26 74.17,87.12 74.17,85.47 TP21.1
  BOTTOM w0.13: TP21.1 73.91,84.96 73.91,84.26 74.17,84.01 74.17,80.87 74,80.71 J2.15
RXNO2-: length 18.2
  TOP w0.13: TP26.1 74.42,87.23 74.29,87.37 74.29,97.35 74.41,97.48 U5.20
  BOTTOM w0.13: TP26.1 74.42,80.78 74.5,80.71 J2.14
RXNO3+: length 19.5
  TOP w0.13: TP23.1 70.36,85.47 70.36,86.85 72.03,88.52 72.03,97.35 71.91,97.48 U5.15
  BOTTOM w0.13: TP23.1 70.1,84.97 70.1,84.26 70.36,84.01 70.36,82.68 71.12,81.92 71.12,80.9 71,80.78 J2.21
RXNO3-: length 19.2
  TOP w0.13: TP28.1 70.61,84.46 70.61,86.74 72.29,88.42 72.29,97.35 72.41,97.48 U5.16
  BOTTOM w0.13: J2.20 71.5,80.71 71.38,80.83 71.38,82.02 70.61,82.79 TP28.1
TLC5910_OUT0: length 27.9
  TOP w0.127: RJ5.3 v3(147.96,94.74) ; v3(137.16,93.73) 137.16,90.17 132.08,85.09 128.91,85.09 128.58,85.42 U12.6
  BOTTOM w0.127: v3(137.16,93.73) 141.1,93.73 141.6,94.23 147.45,94.23 v3(147.96,94.74)
TLC5910_OUT2: length 6
  TOP w0.127: U12.9 126.63,87.89 125.35,89.17 125.35,91.06 RJ13.1
TLC5910_OUT5: length 29.5
  TOP w0.127: v3(137.92,94.61) 137.92,90.17 132.08,84.33 128.65,84.33 126.63,82.31 U12.12 ; RJ4.3 v3(146.05,94.81)
  BOTTOM w0.127: v3(137.92,94.61) 138.42,94.61 138.61,94.81 v3(146.05,94.81)
